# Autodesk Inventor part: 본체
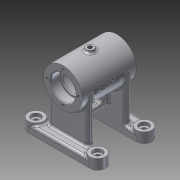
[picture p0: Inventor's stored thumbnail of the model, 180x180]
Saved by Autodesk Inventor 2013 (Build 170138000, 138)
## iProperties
Created: 2015-11
Part Number: 본체
Material: 알루미늄 6061
Document SubType Name: Modeling
Designer: cad10
Density: 2.40731 g/cm^3
Mass: 318.269 g
Surface Area: 455.809 cm^2
Volume: 132.209 cm^3
Author: cad10
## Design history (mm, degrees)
sketch "스케치1"
  geometry: L1 (-40, -20)-(40, -20); L2 (50, -30)-(50, -30); L3 (40, -40)-(-40, -40); L4 (-50, -30)-(-50, -30); L5 (-40, 40)-(40, 40); L6 (50, 30)-(50, 30); L7 (40, 20)-(-40, 20); L8 (-50, 30)-(-50, 30); A1 r 10 centre (-40, 30) between (-40, 40) and (-50, 30); A2 r 10 centre (-40, 30) between (-50, 30) and (-40, 20); A3 r 10 centre (40, 30) between (40, 20) and (50, 30); A4 r 10 centre (40, 30) between (50, 30) and (40, 40); A5 r 10 centre (40, -30) between (50, -30) and (40, -20); A6 r 10 centre (40, -30) between (40, -40) and (50, -30); A7 r 10 centre (-40, -30) between (-50, -30) and (-40, -40); A8 r 10 centre (-40, -30) between (-40, -20) and (-50, -30); 3 further points
  constraints: 16 end point, 16 point on circle, 16 tangent, 8 centre point, 7 equal radius, 4 parallel, 2 horizontal, 2 midpoint, 2 perpendicular, 2 vertical alignment
  dimensions: "d0" = 100 distance between parallel lines of L8 L6; "d2" = 20 distance between parallel lines of L5 L7; "d3" = 20 distance between parallel lines of L3 L1; "d4" = 100 distance between parallel lines of L4 L2; "d5" = 80 distance between parallel lines of L5 L3; "d6" = 40 distance from line of L5 point (0, 0); "d7" = 10 radius of A1
extrude "돌출1" new body sketch "스케치1" distance "d8" = 10; taper "d9" = 0 deg
sketch "스케치2"
  geometry: C1 r 10 at (-40, -30); A1 r 10 centre (40, -30) between (40, -40) and (40, -20) reference; A2 r 10 centre (-40, -30) between (-40, -20) and (-40, -40) reference; 2 further points
  constraints: 2 coincident, 1 centre point, 1 concentric, 1 vertical alignment, 2 other
extrude "돌출2" join sketch "스케치2" distance "d10" = 3; taper "d11" = 0 deg
sketch "스케치3"
  geometry: A1 r 10 centre (-40, 30) between (-40, 40) and (-40, 20) reference; A2 r 10 centre (40, 30) between (40, 20) and (40, 40) reference; 3 further points
  constraints: 2 coincident, 2 vertical alignment, 4 other
extrude "돌출3" join sketch "스케치3" distance "d12" = 3; taper "d13" = 0 deg
node "작업 평면2"
sketch "스케치5"
  geometry: L1 (-40, 0)-(40, 0) reference; C1 r 25 at (0, 68); 2 further points
  constraints: 1 centre point, 1 midpoint, 1 vertical alignment
  dimensions: "d16" = 50 diameter of C1; "d18" = 68 distance from line of C1.centre L1
extrude "돌출4" join sketch "스케치5" stored distance "d19" = 70; taper "d20" = 0 deg
node "작업 평면3"
sketch "스케치6"
  geometry: L1 (-35, 93)-(-35, 43) reference; L2 (35, 43)-(35, 93) reference; L3 (-35, 84)-(-23, 84); L4 (-23, 84)-(-23, 82); L5 (-23, 82)-(-21, 82); L6 (-21, 82)-(-21, 89); L7 (-21, 89)-(21, 89); L8 (21, 89)-(21, 82); L9 (21, 82)-(23, 82); L10 (23, 82)-(23, 84); L11 (23, 84)-(35, 84); L12 (-35, 68)-(35, 68); 1 further point
  constraints: 20 end point, 6 parallel, 3 perpendicular, 2 midpoint, 2 point on line
  dimensions: "d22" = 32 diameter of L3 L12; "d24" = 28 diameter of L5 L12; "d25" = 42 diameter of L7 L12; "d26" = 28 diameter of L9 L12; "d27" = 32 diameter of L11 L12; "d28" = 12 distance between parallel lines of L2 L10; "d29" = 12 distance between parallel lines of L1 L4; "d30" = 42 distance between parallel lines of L8 L6; "d31" = 2 distance between parallel lines of L4 L6
revolve "회전1" sketch "스케치6" stored, may be unused: angle "d32" = 90 deg
sketch "스케치7"
  geometry: L1 (40, -20)-(-40, -20) reference; L2 (-25, -20)-(25, -20); L3 (25, -20)-(25, -28); L4 (25, -28)-(-25, -28); L5 (-25, -28)-(-25, -20); 3 further points
  constraints: 8 end point, 2 midpoint, 2 parallel, 2 vertical alignment, 1 horizontal, 1 perpendicular, 1 point on line
  dimensions: "d33" = 50 distance between parallel lines of L3 L5; "d35" = 8 distance between parallel lines of L1 L4
extrude "돌출5" join sketch "스케치7" stored distance "d38" = 0; taper "d39" = 0 deg
sketch "스케치8"
  geometry: L1 (-40, 20)-(40, 20) reference; L2 (-25, 20)-(25, 20); L3 (25, 20)-(25, 28); L4 (25, 28)-(-25, 28); L5 (-25, 28)-(-25, 20); 3 further points
  constraints: 8 end point, 2 midpoint, 2 parallel, 2 vertical alignment, 1 horizontal, 1 perpendicular, 1 point on line
  dimensions: "d40" = 8 distance between parallel lines of L4 L2; "d42" = 50 distance between parallel lines of L5 L3
extrude "돌출6" join sketch "스케치8" stored distance "d43" = 70; taper "d44" = 0 deg
node "작업 평면4"
sketch "스케치9"
  geometry: C1 r 5 at (0, 0); 1 further point
  constraints: 1 centre point, 1 coincident
  dimensions: "d46" = 10 diameter of C1
extrude "돌출7" join sketch "스케치9" stored distance "d48" = 70; taper "d49" = 0 deg
sketch "스케치10"
  geometry: C1 r 16 at (0, 0) reference; 2 further points
  constraints: 1 vertical alignment
  dimensions: "d50" = 20 distance of point (0, 20) C1.centre
hole "구멍1" sketch "스케치10" at (0, 20) diameter "d51" = 3.242; stored, may be unused: countersink angle "d55" = 90 deg, drill point angle "d57" = 118 deg; dims "d52" = 8, "d53" = 4, "d54" = 2, "d56" = 10
sketch "스케치11"
  geometry: C1 r 10 at (0, 0) reference; 2 further points
  constraints: 1 coincident
hole "구멍2" sketch "스케치11" at (0, 0) diameter "d61" = 6; stored, may be unused: countersink angle "d65" = 90 deg, drill point angle "d67" = 0 deg; dims "d62" = 5.946, "d63" = 12, "d64" = 4, "d66" = 13
sketch "스케치12"
  geometry: C1 r 5 at (0, 0) reference; 1 further point
  constraints: 1 coincident
hole "구멍3" sketch "스케치12" at (0, 0) diameter "d68" = 5.188; stored, may be unused: countersink angle "d72" = 90 deg, drill point angle "d74" = 118 deg; dims "d69" = 6, "d70" = 12, "d71" = 4, "d73" = 13
node "작업 평면5"
sketch "스케치13"
  geometry: L1 (40, 20)-(-40, 20) reference; L2 (40, -20)-(-40, -20) reference; L3 (-4, 20)-(4, 20); L4 (4, 20)-(4, -20); L5 (4, -20)-(-4, -20); L6 (-4, -20)-(-4, 20); 2 further points
  constraints: 8 end point, 2 parallel, 2 point on line, 1 horizontal, 1 midpoint, 1 perpendicular, 1 vertical alignment
  dimensions: "d76" = 8 distance between parallel lines of L4 L6
extrude "돌출8" join sketch "스케치13" stored distance "d78" = 70; taper "d79" = 0 deg
sketch "스케치14" dims "d82" = 23
  geometry: L1 (6.5, 28)-(6.5, 12); L2 (13.5, 12)-(13.5, 28); A1 r 3.5 centre (10, 28) between (13.5, 28) and (10, 31.5); A2 r 3.5 centre (10, 28) between (10, 31.5) and (6.5, 28); A3 r 3.5 centre (10, 12) between (6.5, 12) and (10, 8.5); A4 r 3.5 centre (10, 12) between (10, 8.5) and (13.5, 12); 2 further points; 2 other entities
  constraints: 8 point on circle, 4 centre point, 4 end point, 4 tangent, 3 equal radius, 2 coincident, 1 horizontal alignment, 1 midpoint, 1 parallel, 1 vertical, 8 other
  dimensions: "d80" = 7 distance between parallel lines of L1 L2; "d83" = 3.5 radius of A1; "d84" = 33 horizontal distance of A1.centre point (-23, 20)
extrude "돌출9" cut sketch "스케치14" stored distance "d85" = 10; taper "d86" = 0 deg
node "작업 평면9"
  node "작업 평면8"
sketch "스케치16"
  geometry: L1 (-35, 93)-(-35, 43) reference; L2 (35, 93)-(-35, 93) reference; 2 further points
  constraints: 1 other
  dimensions: "d91" = 35 distance from line of L1 point (0, 68); "d92" = 25 distance from line of L2 point (0, 68)
feature "엠보싱1" sketch "스케치16" dims "d0" = 100, "d2" = 20, "d3" = 20, "d4" = 100, "d5" = 80, "d6" = 40, "d7" = 10, "d93" = 0.5, "d94" = 0
node "작업 평면10"
fillet "모깎기1" dims "d96" = 3
fillet "모깎기2" dims "d97" = 3
fillet "모깎기3" dims "d98" = 3
fillet "모깎기4" dims "d99" = 3
node "작업 평면15"
  node "작업 평면14"
sketch "스케치19"
  geometry: C1 r 6 at (0, 3.89); 1 further point
  constraints: 1 centre point, 1 vertical alignment
  dimensions: "d108" = 12 diameter of C1; "d110" = 55 distance of point (0, 58.89) C1.centre
extrude "돌출10" join sketch "스케치19" stored distance "d111" = 10; taper "d112" = 0 deg
sketch "스케치20"
  geometry: C1 r 6 at (0, 0) reference; 2 further points
  constraints: 1 coincident
hole "구멍4" sketch "스케치20" at (0, 0) diameter "d113" = 5.188; stored, may be unused: countersink angle "d117" = 90 deg, drill point angle "d119" = 0 deg; dims "d114" = 6, "d115" = 4, "d116" = 2, "d118" = 8
fillet "모깎기5" dims "d120" = 3
chamfer "모따기1" distance "d121" = 1; stored, may be unused: second distance "d122" = 2, angle "d123" = 45 deg
fillet "모깎기6" dims "d124" = 3
fillet "모깎기7" dims "d125" = 0.3
node "작업축3"
fillet "모깎기8" dims "d126" = 0.3
node "솔리드1"
pattern_circular "원형 패턴1" dims angle "d59" = 360 deg
mirror "대칭1"
mirror "대칭2"
mirror "대칭3"
node "작업축2"
other parameters: "d15" = 90 deg, "d21" = 90 deg, "d45" = 96, "d75" = 23, "d89" = 90 deg, "d90" = 25.5, "d95" = 90 deg, "d106" = 30 deg, "d107" = -28
